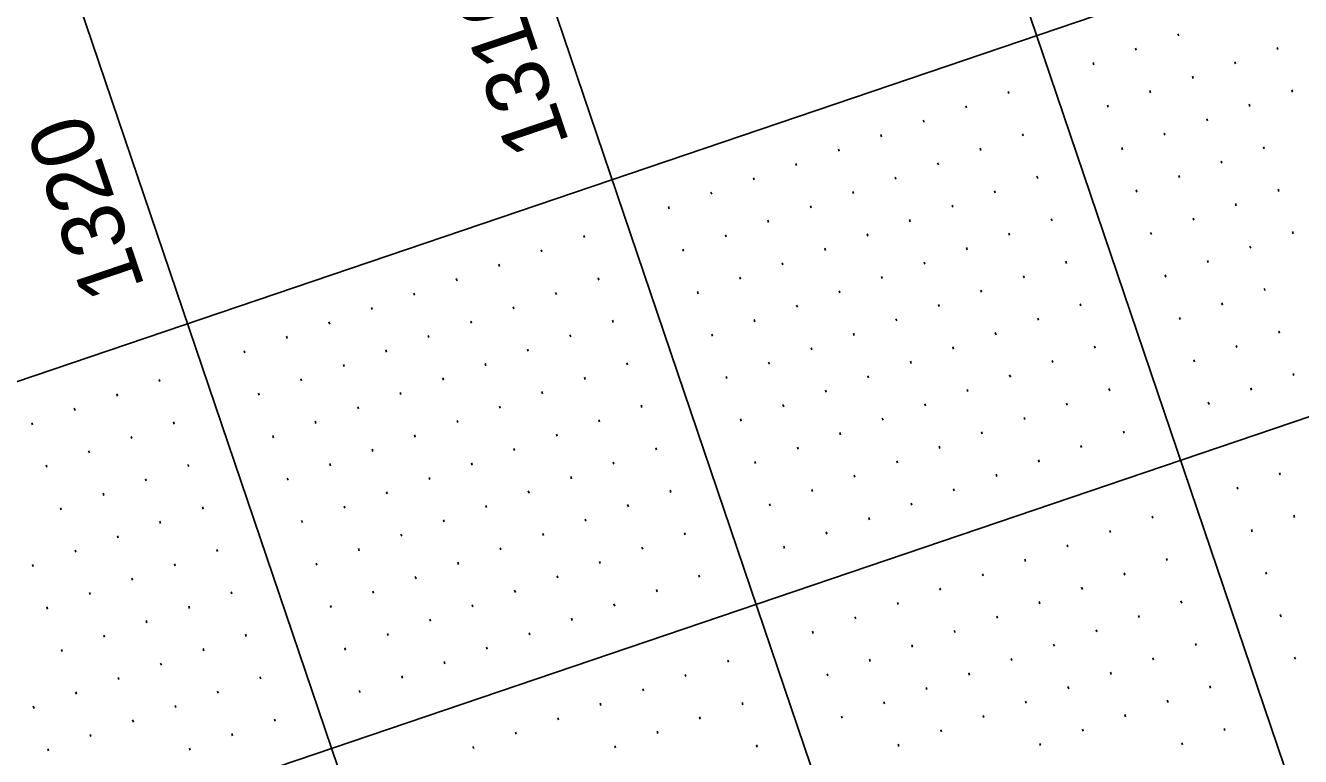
# Model space of a CAD drawing. Extents: x 2150318 to 2152065, y 143281 to 145371.
# Drawn here: x 2151036.1 to 2151178.4, y 145098.8 to 145180.3 of the extents above; entities that cross this region are included whole.
import ezdxf

# ---------------------------------------------------------------- set-up
doc = ezdxf.new("R2010")
doc.units = 0
for name, color, linetype in [('SHT_Plan_Profile_Sheet_Elev_Txt', 7, 'Continuous'), ('SHT_Profile_Grid_Major', 7, 'Continuous'), ('SHT_Profile_Grid_Minor', 7, 'Continuous'), ('SHT_Sheet_Border', 7, 'Continuous')]:
    doc.layers.add(name, color=color, linetype=linetype)

msp = doc.modelspace()

# ---------------------------------------------------------------- linework, layer by layer
at = {"layer": 'SHT_Profile_Grid_Major'}
for p, q in [((2151642.87, 143723.15), (2151136.88, 145214.66)), ((2151595.52, 143707.09), (2151089.53, 145198.6)), ((2151548.17, 143691.03), (2151042.18, 145182.54)), ((2151307.04, 145179.99), (2150928.24, 145051.49))]:
    msp.add_line(p, q, dxfattribs=at)
at = {"layer": 'SHT_Profile_Grid_Minor'}
for p, q in [((2151164.78, 145179.12), (2151164.69, 145179.35)), ((2151160.04, 145177.51), (2151159.96, 145177.75)), ((2151175.85, 145177.59), (2151175.77, 145177.83)), ((2151155.31, 145175.9), (2151155.23, 145176.14)), ((2151171.12, 145175.99), (2151171.04, 145176.23)), ((2151166.38, 145174.38), (2151166.3, 145174.62)), ((2151145.84, 145172.69), (2151145.76, 145172.93)), ((2151161.65, 145172.78), (2151161.57, 145173.01)), ((2151177.46, 145172.86), (2151177.38, 145173.1)), ((2151141.1, 145171.09), (2151141.02, 145171.32)), ((2151156.91, 145171.17), (2151156.83, 145171.41)), ((2151172.72, 145171.25), (2151172.64, 145171.49)), ((2151136.37, 145169.48), (2151136.29, 145169.72)), ((2151167.99, 145169.65), (2151167.91, 145169.88)), ((2151131.63, 145167.87), (2151131.55, 145168.11)), ((2151147.44, 145167.96), (2151147.36, 145168.19)), ((2151163.25, 145168.04), (2151163.17, 145168.28)), ((2151126.9, 145166.27), (2151126.82, 145166.5)), ((2151142.71, 145166.35), (2151142.63, 145166.59)), ((2151158.52, 145166.43), (2151158.44, 145166.67)), ((2151174.33, 145166.52), (2151174.25, 145166.76)), ((2151122.16, 145164.66), (2151122.08, 145164.9)), ((2151137.97, 145164.74), (2151137.89, 145164.98)), ((2151169.59, 145164.91), (2151169.51, 145165.15)), ((2151117.43, 145163.05), (2151117.35, 145163.29)), ((2151133.24, 145163.14), (2151133.16, 145163.37)), ((2151149.05, 145163.22), (2151148.97, 145163.46)), ((2151164.86, 145163.31), (2151164.78, 145163.54)), ((2151128.5, 145161.53), (2151128.42, 145161.77)), ((2151144.31, 145161.62), (2151144.23, 145161.85)), ((2151160.12, 145161.7), (2151160.04, 145161.94)), ((2151175.94, 145161.78), (2151175.86, 145162.02)), ((2151112.69, 145161.45), (2151112.61, 145161.68)), ((2151171.2, 145160.18), (2151171.12, 145160.41)), ((2151107.96, 145159.84), (2151107.88, 145160.08)), ((2151123.77, 145159.93), (2151123.69, 145160.16)), ((2151139.58, 145160.01), (2151139.5, 145160.25)), ((2151119.03, 145158.32), (2151118.95, 145158.56)), ((2151134.84, 145158.4), (2151134.76, 145158.64)), ((2151150.65, 145158.49), (2151150.57, 145158.72)), ((2151166.47, 145158.57), (2151166.39, 145158.81)), ((2151098.49, 145156.63), (2151098.41, 145156.87)), ((2151114.3, 145156.71), (2151114.22, 145156.95)), ((2151130.11, 145156.8), (2151130.03, 145157.03)), ((2151145.92, 145156.88), (2151145.84, 145157.12)), ((2151161.73, 145156.96), (2151161.65, 145157.2)), ((2151177.54, 145157.05), (2151177.46, 145157.29)), ((2151093.75, 145155.02), (2151093.67, 145155.26)), ((2151109.56, 145155.11), (2151109.48, 145155.34)), ((2151125.37, 145155.19), (2151125.29, 145155.43)), ((2151141.18, 145155.27), (2151141.1, 145155.51)), ((2151172.81, 145155.44), (2151172.73, 145155.68)), ((2151089.02, 145153.42), (2151088.94, 145153.65)), ((2151120.64, 145153.58), (2151120.56, 145153.82)), ((2151136.45, 145153.67), (2151136.37, 145153.9)), ((2151152.26, 145153.75), (2151152.18, 145153.99)), ((2151168.07, 145153.84), (2151167.99, 145154.07)), ((2151084.28, 145151.81), (2151084.2, 145152.05)), ((2151100.09, 145151.89), (2151100.01, 145152.13)), ((2151115.9, 145151.98), (2151115.82, 145152.21)), ((2151131.71, 145152.06), (2151131.63, 145152.3)), ((2151147.53, 145152.15), (2151147.45, 145152.38)), ((2151163.34, 145152.23), (2151163.26, 145152.47)), ((2151079.55, 145150.2), (2151079.47, 145150.44)), ((2151095.36, 145150.29), (2151095.28, 145150.52)), ((2151111.17, 145150.37), (2151111.09, 145150.61)), ((2151126.98, 145150.46), (2151126.9, 145150.69)), ((2151142.79, 145150.54), (2151142.71, 145150.78)), ((2151174.41, 145150.71), (2151174.33, 145150.94)), ((2151122.24, 145148.85), (2151122.16, 145149.09)), ((2151138.06, 145148.93), (2151137.98, 145149.17)), ((2151153.87, 145149.02), (2151153.79, 145149.25)), ((2151169.68, 145149.1), (2151169.6, 145149.34)), ((2151074.81, 145148.6), (2151074.73, 145148.83)), ((2151090.62, 145148.68), (2151090.54, 145148.92)), ((2151133.32, 145147.33), (2151133.24, 145147.56)), ((2151149.13, 145147.41), (2151149.05, 145147.65)), ((2151164.94, 145147.49), (2151164.86, 145147.73)), ((2151070.08, 145146.99), (2151070, 145147.23)), ((2151085.89, 145147.07), (2151085.81, 145147.31)), ((2151101.7, 145147.16), (2151101.62, 145147.4)), ((2151117.51, 145147.24), (2151117.43, 145147.48)), ((2151176.02, 145145.97), (2151175.94, 145146.21)), ((2151065.34, 145145.38), (2151065.26, 145145.62)), ((2151081.15, 145145.47), (2151081.07, 145145.71)), ((2151096.96, 145145.55), (2151096.88, 145145.79)), ((2151112.77, 145145.64), (2151112.69, 145145.87)), ((2151128.59, 145145.72), (2151128.51, 145145.96)), ((2151144.4, 145145.8), (2151144.32, 145146.04)), ((2151060.61, 145143.78), (2151060.53, 145144.01)), ((2151076.42, 145143.86), (2151076.34, 145144.1)), ((2151092.23, 145143.95), (2151092.15, 145144.18)), ((2151123.85, 145144.11), (2151123.77, 145144.35)), ((2151139.66, 145144.2), (2151139.58, 145144.43)), ((2151155.47, 145144.28), (2151155.39, 145144.52)), ((2151171.28, 145144.37), (2151171.2, 145144.6)), ((2151071.68, 145142.26), (2151071.6, 145142.49)), ((2151087.49, 145142.34), (2151087.41, 145142.58)), ((2151103.3, 145142.42), (2151103.22, 145142.66)), ((2151119.12, 145142.51), (2151119.04, 145142.74)), ((2151134.93, 145142.59), (2151134.85, 145142.83)), ((2151150.74, 145142.68), (2151150.66, 145142.91)), ((2151166.55, 145142.76), (2151166.47, 145143)), ((2151051.14, 145140.57), (2151051.06, 145140.8)), ((2151066.95, 145140.65), (2151066.87, 145140.89)), ((2151082.76, 145140.73), (2151082.68, 145140.97)), ((2151098.57, 145140.82), (2151098.49, 145141.05)), ((2151114.38, 145140.9), (2151114.3, 145141.14)), ((2151130.19, 145140.99), (2151130.11, 145141.22)), ((2151146, 145141.07), (2151145.92, 145141.31)), ((2151177.63, 145141.24), (2151177.55, 145141.47)), ((2151046.4, 145138.96), (2151046.32, 145139.2)), ((2151062.21, 145139.04), (2151062.13, 145139.28)), ((2151078.02, 145139.13), (2151077.94, 145139.36)), ((2151093.83, 145139.21), (2151093.75, 145139.45)), ((2151125.46, 145139.38), (2151125.38, 145139.62)), ((2151141.27, 145139.46), (2151141.19, 145139.7)), ((2151157.08, 145139.55), (2151157, 145139.78)), ((2151172.89, 145139.63), (2151172.81, 145139.87)), ((2151041.67, 145137.35), (2151041.59, 145137.59)), ((2151073.29, 145137.52), (2151073.21, 145137.76)), ((2151089.1, 145137.6), (2151089.02, 145137.84)), ((2151104.91, 145137.69), (2151104.83, 145137.93)), ((2151120.72, 145137.77), (2151120.64, 145138.01)), ((2151136.53, 145137.86), (2151136.45, 145138.09)), ((2151152.34, 145137.94), (2151152.26, 145138.18)), ((2151168.16, 145138.03), (2151168.08, 145138.26)), ((2151084.37, 145136), (2151084.28, 145136.24)), ((2151100.18, 145136.08), (2151100.1, 145136.32)), ((2151115.99, 145136.17), (2151115.91, 145136.4)), ((2151131.8, 145136.25), (2151131.72, 145136.49)), ((2151147.61, 145136.33), (2151147.53, 145136.57)), ((2151036.93, 145135.75), (2151036.85, 145135.98)), ((2151052.74, 145135.83), (2151052.66, 145136.07)), ((2151068.55, 145135.91), (2151068.47, 145136.15)), ((2151127.06, 145134.64), (2151126.98, 145134.88)), ((2151142.87, 145134.73), (2151142.79, 145134.97)), ((2151158.69, 145134.81), (2151158.61, 145135.05)), ((2151048.01, 145134.22), (2151047.93, 145134.46)), ((2151063.82, 145134.31), (2151063.74, 145134.55)), ((2151079.63, 145134.39), (2151079.55, 145134.63)), ((2151095.44, 145134.48), (2151095.36, 145134.71)), ((2151138.14, 145133.12), (2151138.06, 145133.36)), ((2151153.95, 145133.21), (2151153.87, 145133.44)), ((2151043.27, 145132.62), (2151043.19, 145132.85)), ((2151074.9, 145132.79), (2151074.81, 145133.02)), ((2151090.71, 145132.87), (2151090.63, 145133.11)), ((2151106.52, 145132.95), (2151106.44, 145133.19)), ((2151122.33, 145133.04), (2151122.25, 145133.27)), ((2151038.54, 145131.01), (2151038.46, 145131.25)), ((2151054.35, 145131.1), (2151054.27, 145131.33)), ((2151070.16, 145131.18), (2151070.08, 145131.42)), ((2151085.97, 145131.26), (2151085.89, 145131.5)), ((2151101.78, 145131.35), (2151101.7, 145131.58)), ((2151117.59, 145131.43), (2151117.51, 145131.67)), ((2151133.4, 145131.52), (2151133.32, 145131.75)), ((2151149.22, 145131.6), (2151149.14, 145131.84)), ((2151049.61, 145129.49), (2151049.53, 145129.73)), ((2151065.43, 145129.57), (2151065.35, 145129.81)), ((2151081.24, 145129.66), (2151081.16, 145129.89)), ((2151097.05, 145129.74), (2151096.97, 145129.98)), ((2151128.67, 145129.91), (2151128.59, 145130.15)), ((2151144.48, 145129.99), (2151144.4, 145130.23)), ((2151176.1, 145130.16), (2151176.02, 145130.4)), ((2151044.88, 145127.88), (2151044.8, 145128.12)), ((2151076.5, 145128.05), (2151076.42, 145128.29)), ((2151092.31, 145128.14), (2151092.23, 145128.37)), ((2151108.12, 145128.22), (2151108.04, 145128.46)), ((2151123.94, 145128.3), (2151123.85, 145128.54)), ((2151139.75, 145128.39), (2151139.67, 145128.62)), ((2151171.37, 145128.56), (2151171.29, 145128.79)), ((2151040.14, 145126.28), (2151040.06, 145126.51)), ((2151055.96, 145126.36), (2151055.88, 145126.6)), ((2151071.77, 145126.44), (2151071.69, 145126.68)), ((2151087.58, 145126.53), (2151087.5, 145126.77)), ((2151103.39, 145126.61), (2151103.31, 145126.85)), ((2151119.2, 145126.7), (2151119.12, 145126.93)), ((2151135.01, 145126.78), (2151134.93, 145127.02)), ((2151051.22, 145124.75), (2151051.14, 145124.99)), ((2151067.03, 145124.84), (2151066.95, 145125.08)), ((2151082.84, 145124.92), (2151082.76, 145125.16)), ((2151098.65, 145125.01), (2151098.57, 145125.24)), ((2151130.28, 145125.17), (2151130.2, 145125.41)), ((2151161.9, 145125.34), (2151161.82, 145125.58)), ((2151177.71, 145125.43), (2151177.63, 145125.66)), ((2151046.49, 145123.15), (2151046.41, 145123.38)), ((2151078.11, 145123.32), (2151078.03, 145123.55)), ((2151093.92, 145123.4), (2151093.84, 145123.64)), ((2151109.73, 145123.48), (2151109.65, 145123.72)), ((2151125.54, 145123.57), (2151125.46, 145123.8)), ((2151157.16, 145123.74), (2151157.08, 145123.97)), ((2151172.97, 145123.82), (2151172.89, 145124.06)), ((2151073.37, 145121.71), (2151073.29, 145121.95)), ((2151089.18, 145121.79), (2151089.1, 145122.03)), ((2151105, 145121.88), (2151104.91, 145122.11)), ((2151120.81, 145121.96), (2151120.73, 145122.2)), ((2151152.43, 145122.13), (2151152.35, 145122.37)), ((2151041.75, 145121.54), (2151041.67, 145121.78)), ((2151057.56, 145121.63), (2151057.48, 145121.86)), ((2151147.69, 145120.52), (2151147.61, 145120.76)), ((2151163.5, 145120.61), (2151163.42, 145120.84)), ((2151037.02, 145119.94), (2151036.94, 145120.17)), ((2151052.83, 145120.02), (2151052.75, 145120.26)), ((2151068.64, 145120.1), (2151068.56, 145120.34)), ((2151084.45, 145120.19), (2151084.37, 145120.42)), ((2151100.26, 145120.27), (2151100.18, 145120.51)), ((2151142.96, 145118.92), (2151142.88, 145119.15)), ((2151158.77, 145119), (2151158.69, 145119.24)), ((2151174.58, 145119.09), (2151174.5, 145119.32)), ((2151048.09, 145118.41), (2151048.01, 145118.65)), ((2151079.71, 145118.58), (2151079.63, 145118.82)), ((2151095.53, 145118.67), (2151095.44, 145118.9)), ((2151111.34, 145118.75), (2151111.26, 145118.99)), ((2151043.36, 145116.81), (2151043.28, 145117.04)), ((2151059.17, 145116.89), (2151059.09, 145117.13)), ((2151074.98, 145116.97), (2151074.9, 145117.21)), ((2151090.79, 145117.06), (2151090.71, 145117.3)), ((2151106.6, 145117.14), (2151106.52, 145117.38)), ((2151138.22, 145117.31), (2151138.14, 145117.55)), ((2151154.04, 145117.39), (2151153.95, 145117.63)), ((2151038.62, 145115.2), (2151038.54, 145115.44)), ((2151054.43, 145115.28), (2151054.35, 145115.52)), ((2151070.24, 145115.37), (2151070.16, 145115.61)), ((2151086.06, 145115.45), (2151085.98, 145115.69)), ((2151101.87, 145115.54), (2151101.79, 145115.77)), ((2151133.49, 145115.7), (2151133.41, 145115.94)), ((2151149.3, 145115.79), (2151149.22, 145116.03)), ((2151165.11, 145115.87), (2151165.03, 145116.11)), ((2151049.7, 145113.68), (2151049.62, 145113.91)), ((2151081.32, 145113.85), (2151081.24, 145114.08)), ((2151097.13, 145113.93), (2151097.05, 145114.17)), ((2151128.75, 145114.1), (2151128.67, 145114.33)), ((2151144.57, 145114.18), (2151144.48, 145114.42)), ((2151160.38, 145114.27), (2151160.3, 145114.5)), ((2151176.19, 145114.35), (2151176.11, 145114.59)), ((2151044.96, 145112.07), (2151044.88, 145112.31)), ((2151060.77, 145112.16), (2151060.69, 145112.39)), ((2151076.59, 145112.24), (2151076.51, 145112.48)), ((2151092.4, 145112.32), (2151092.32, 145112.56)), ((2151124.02, 145112.49), (2151123.94, 145112.73)), ((2151139.83, 145112.58), (2151139.75, 145112.81)), ((2151155.64, 145112.66), (2151155.56, 145112.9)), ((2151040.23, 145110.47), (2151040.15, 145110.7)), ((2151056.04, 145110.55), (2151055.96, 145110.79)), ((2151071.85, 145110.63), (2151071.77, 145110.87)), ((2151087.66, 145110.72), (2151087.58, 145110.95)), ((2151135.1, 145110.97), (2151135.01, 145111.21)), ((2151150.91, 145111.05), (2151150.83, 145111.29)), ((2151166.72, 145111.14), (2151166.64, 145111.37)), ((2151051.3, 145108.94), (2151051.22, 145109.18)), ((2151082.93, 145109.11), (2151082.85, 145109.35)), ((2151114.55, 145109.28), (2151114.47, 145109.52)), ((2151130.36, 145109.36), (2151130.28, 145109.6)), ((2151146.17, 145109.45), (2151146.09, 145109.68)), ((2151161.98, 145109.53), (2151161.9, 145109.77)), ((2151177.79, 145109.62), (2151177.71, 145109.85)), ((2151078.19, 145107.51), (2151078.11, 145107.74)), ((2151109.81, 145107.67), (2151109.73, 145107.91)), ((2151125.63, 145107.76), (2151125.55, 145107.99)), ((2151141.44, 145107.84), (2151141.36, 145108.08)), ((2151157.25, 145107.92), (2151157.17, 145108.16)), ((2151046.57, 145107.34), (2151046.49, 145107.57)), ((2151062.38, 145107.42), (2151062.3, 145107.66)), ((2151105.08, 145106.07), (2151105, 145106.3)), ((2151136.7, 145106.23), (2151136.62, 145106.47)), ((2151152.51, 145106.32), (2151152.43, 145106.56)), ((2151168.32, 145106.4), (2151168.24, 145106.64)), ((2151041.83, 145105.73), (2151041.75, 145105.97)), ((2151057.65, 145105.81), (2151057.57, 145106.05)), ((2151073.46, 145105.9), (2151073.38, 145106.14)), ((2151147.78, 145104.71), (2151147.7, 145104.95)), ((2151163.59, 145104.8), (2151163.51, 145105.03)), ((2151037.1, 145104.12), (2151037.02, 145104.36)), ((2151052.91, 145104.21), (2151052.83, 145104.45)), ((2151100.34, 145104.46), (2151100.26, 145104.7)), ((2151116.16, 145104.54), (2151116.08, 145104.78)), ((2151131.97, 145104.63), (2151131.89, 145104.87)), ((2151048.18, 145102.6), (2151048.1, 145102.84)), ((2151063.99, 145102.69), (2151063.91, 145102.92)), ((2151095.61, 145102.85), (2151095.53, 145103.09)), ((2151111.42, 145102.94), (2151111.34, 145103.17)), ((2151127.23, 145103.02), (2151127.15, 145103.26)), ((2151143.04, 145103.11), (2151142.96, 145103.34)), ((2151158.85, 145103.19), (2151158.77, 145103.43)), ((2151043.44, 145101), (2151043.36, 145101.23)), ((2151059.25, 145101.08), (2151059.17, 145101.32)), ((2151090.87, 145101.25), (2151090.79, 145101.48)), ((2151106.69, 145101.33), (2151106.61, 145101.57)), ((2151138.31, 145101.5), (2151138.23, 145101.74)), ((2151154.12, 145101.58), (2151154.04, 145101.82)), ((2151169.93, 145101.67), (2151169.85, 145101.9)), ((2151038.71, 145099.39), (2151038.63, 145099.63)), ((2151054.52, 145099.47), (2151054.44, 145099.71)), ((2151086.14, 145099.64), (2151086.06, 145099.88)), ((2151101.95, 145099.73), (2151101.87, 145099.96)), ((2151117.76, 145099.81), (2151117.68, 145100.05)), ((2151133.57, 145099.89), (2151133.49, 145100.13)), ((2151149.38, 145099.98), (2151149.3, 145100.21)), ((2151165.2, 145100.06), (2151165.11, 145100.3))]:
    msp.add_line(p, q, dxfattribs=at)
at = {"layer": 'SHT_Sheet_Border'}
msp.add_line((2151362, 145251.44), (2150912.18, 145098.84), dxfattribs=at)

# ---------------------------------------------------------------- texts
at = {"layer": 'SHT_Plan_Profile_Sheet_Elev_Txt'}
for s, p in [('1310', (2151096.85, 145167.18)), ('1320', (2151049.5, 145151.12))]:
    msp.add_text(s, height=7, rotation=108.7393, dxfattribs=at).set_placement(p)

doc.saveas('drawing.dxf')
